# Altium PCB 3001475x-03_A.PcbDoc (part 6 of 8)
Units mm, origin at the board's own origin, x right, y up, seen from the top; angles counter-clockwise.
Board outline 100 x 72 mm, 12 copper layers (Top Layer, L2 GND, Layer 3, L4 GND, Layer 5, L6 PWR, L7 3V3, Layer 8, L9 GND, Layer 10, L11 GND, Bottom Layer), stack 1.735 mm thick; 428 components, 499 nets, 1973 pads, 1473 vias.
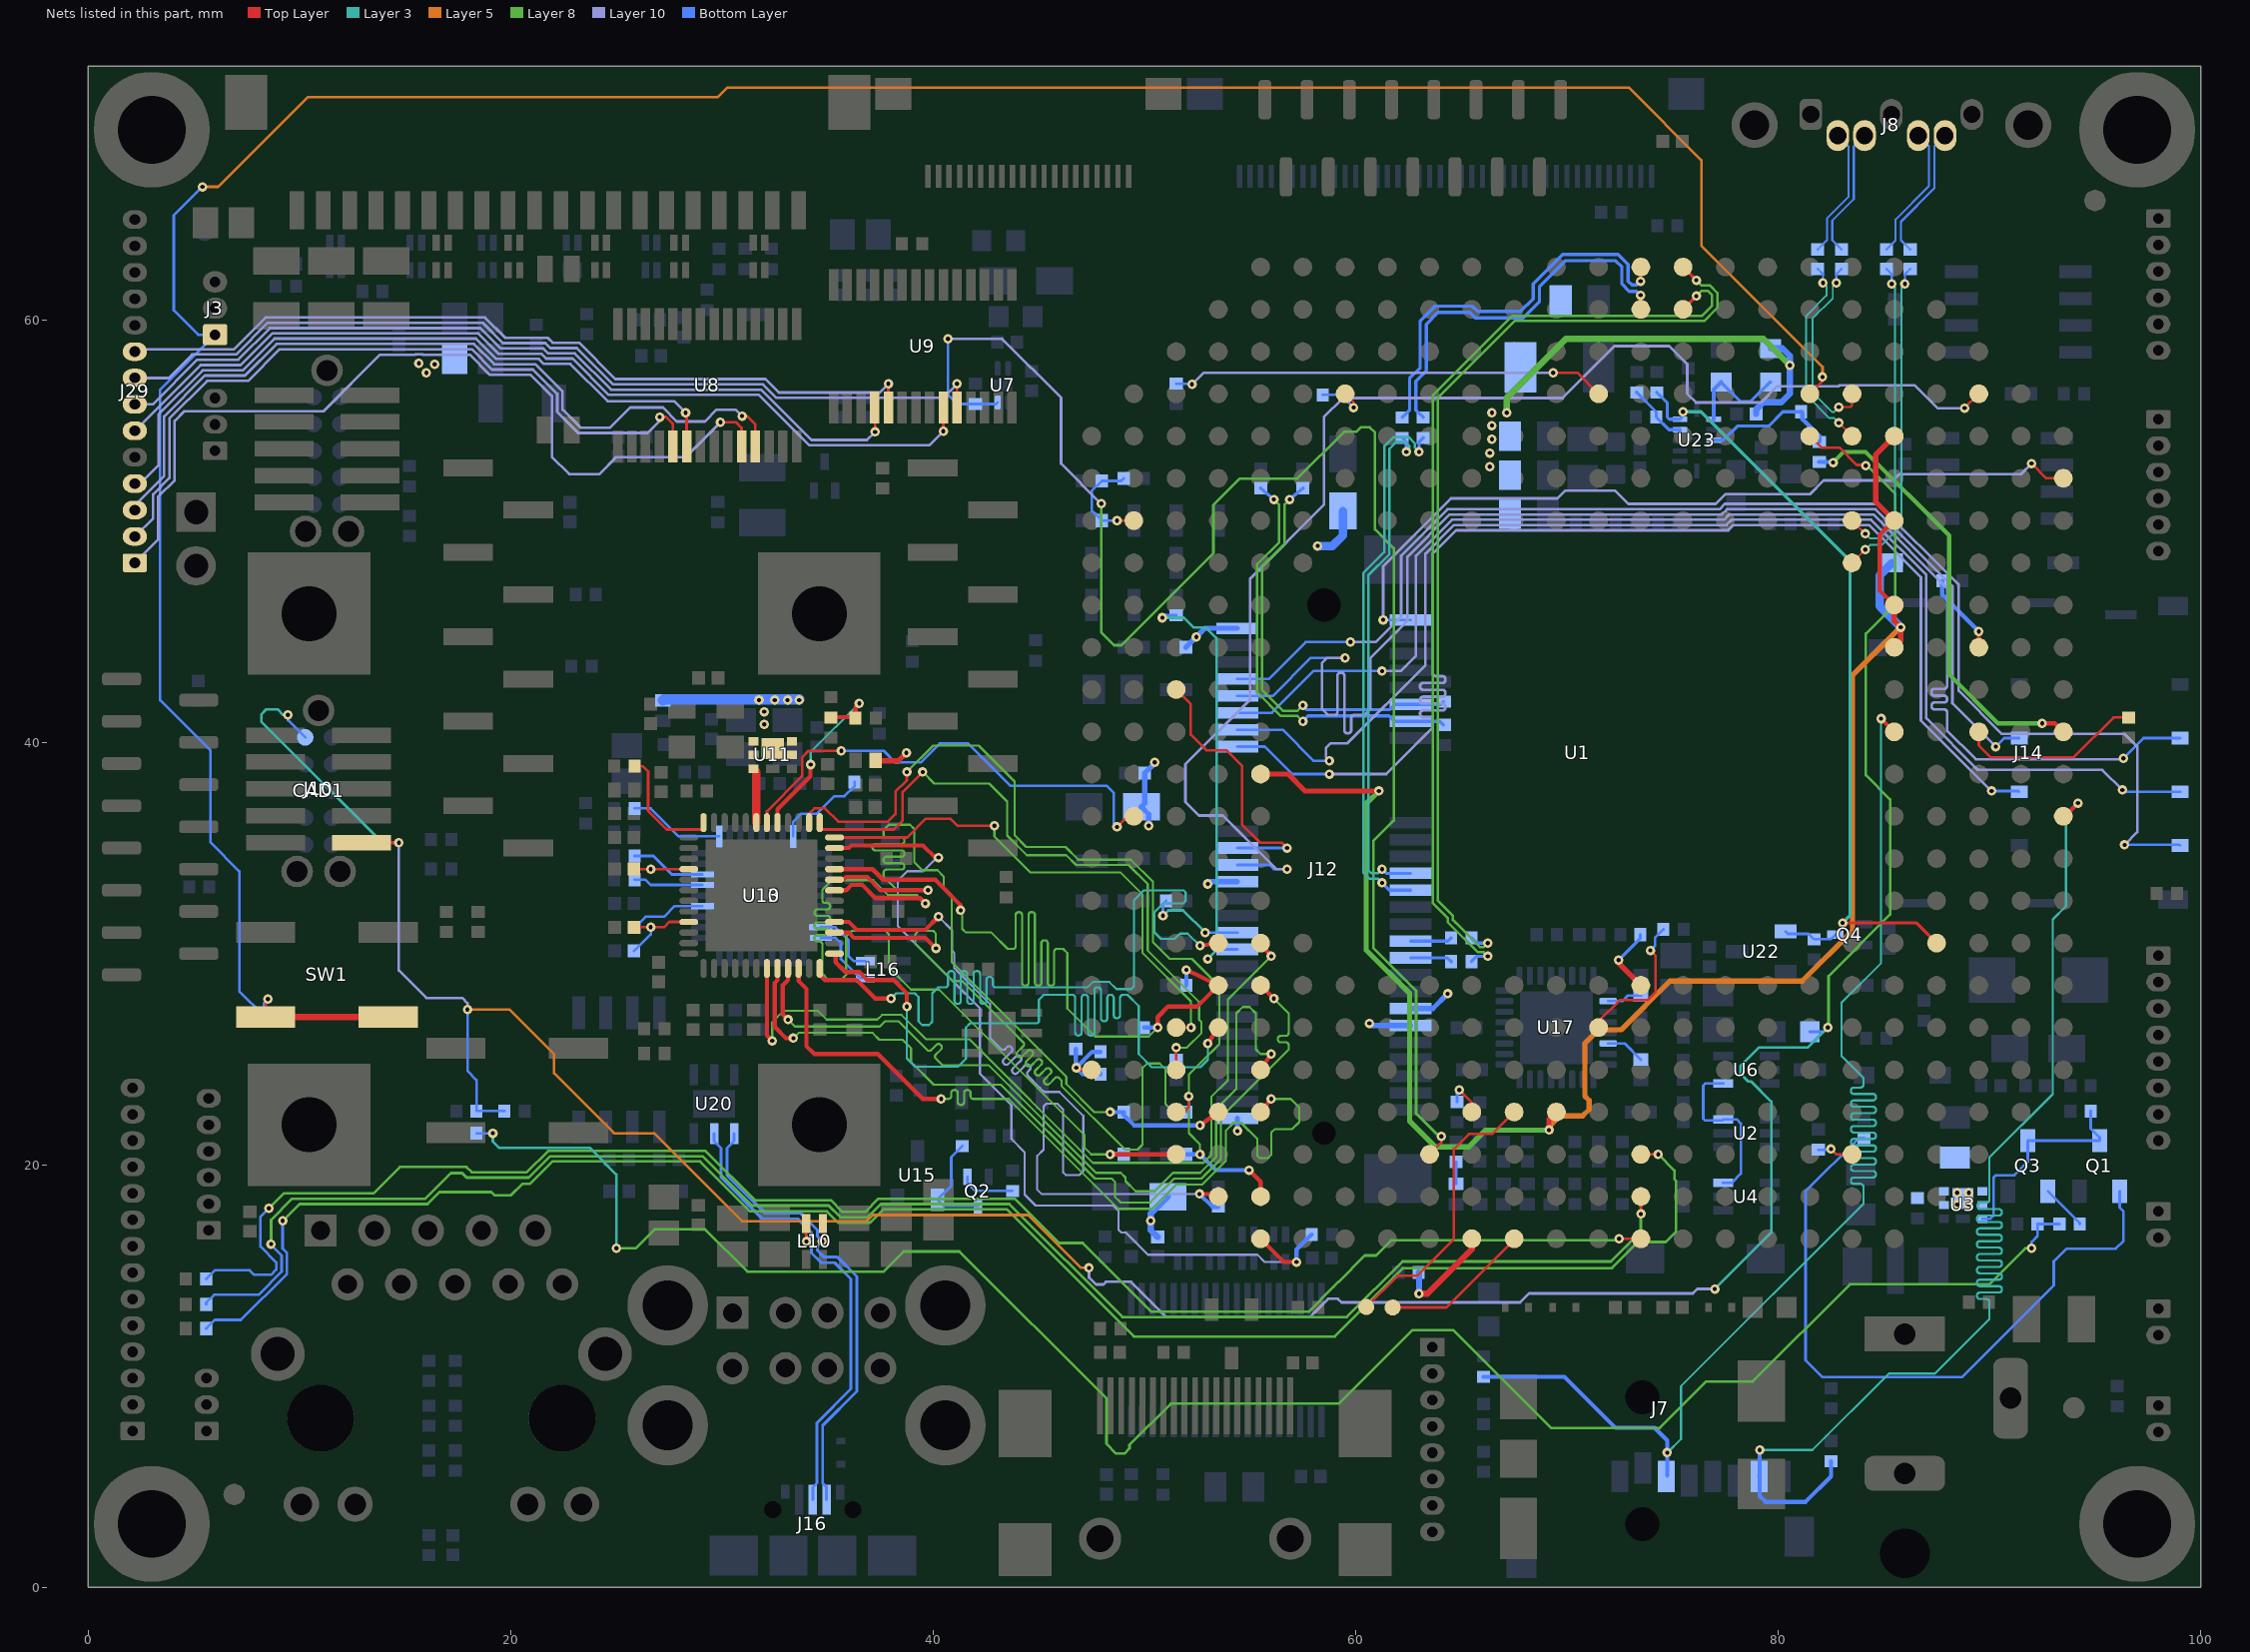
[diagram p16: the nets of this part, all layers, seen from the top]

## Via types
v1: diameter 0.45, hole 0.2, Top Layer to Bottom Layer, 1473 vias

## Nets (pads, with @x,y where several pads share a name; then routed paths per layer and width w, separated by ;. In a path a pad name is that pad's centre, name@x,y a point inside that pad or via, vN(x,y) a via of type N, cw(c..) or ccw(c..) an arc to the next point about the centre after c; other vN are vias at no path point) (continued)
NetL16_1: L16.1 U13.8 | length 3.2
  Bottom Layer w0.125: U13.8@34.675,31.25 35.375,31.25 36,30.625 36,29.875 36.225,29.65 L16.1@36.775,29.65
NetL16_4: L16.4 U13.9 | length 3.3
  Bottom Layer w0.125: U13.9@34.675,30.75 35.375,30.75 35.625,30.5 35.625,29.75 36.525,28.85 L16.4@36.775,28.85
NetL23_2: L23.2 R94.1 | length 1
  Bottom Layer w0.125: L23.2@64.75,19.105 R94.1@64.75,20.145
NetL24_1: L24.1 U17.2 | length 1.7
  Bottom Layer w0.125: U17.2@71.95,27.75 72.625,27.75 72.895,28.02 L24.1@73.5,28.02
NetL25_1: L25.1 U17.6 | length 1.9
  Bottom Layer w0.125: U17.6@71.95,25.75 72.73,25.75 L25.1@73.5,24.98
NetQ1_1: Q1.1 R13.2 | length 33
  Bottom Layer w0.125: R13.2@84.07,21.27 83.82,21.27 81.3,18.75 81.3,10.75 82.097,9.953 88.703,9.953 93.05,14.3 93.05,15.433 93.654,16.037 95.987,16.037 96.35,16.4 96.35,17.8 96.17,17.98 Q1.1@96.17,18.75
NetQ1_3: Q1.3 Q3.3 R14.2 U3.3 | length 10.3
  Bottom Layer w0.125: U3.3@89.66,17.45 90.05,17.45 90.2,17.6 90.2,19.4 90.313,19.513 91.183,19.513 91.82,20.15 Q3.3@91.82,21.15 Q1.3@95.22,21.15 95.22,21.3 94.8,21.72 R14.2@94.8,22.55
NetQ2_D: Q2.D R72.2 U15.G | length 5.1
  Bottom Layer w0.125: R72.2@41.375,20.895 40.85,20.37 40.85,19 U15.G@40.2,18.35 40.49,18.06 Q2.D@42.125,18.06
NetQ2_G: Q2.G R75.2 | length 2.6
  Bottom Layer w0.125: Q2.G@41.625,19.44 41.625,19.125 41.98,18.77 R75.2@43.75,18.77
NetQ3_1: Q3.1 R125.2 | length 2.2
  Bottom Layer w0.125: Q3.1@92.77,18.75 94.28,17.24 R125.2@94.28,17.2
NetQ4_D: Q4.D R128.2 U22.G | length 2.6
  Bottom Layer w0.125: U22.G@80.35,31.05 80.463,30.937 81.442,30.937 R128.2@81.7,30.68 82.49,30.68 Q4.D@82.71,30.9
NetR1_1: R1.1 R2.1 R3.1 U1.G2 | length 4.9
  Top Layer w0.125: v1(48.7,50.5) U1.G2@49.5,50.5
  Bottom Layer w0.125: v1(48.7,50.5) R1.1@47.98,50.5 47.5,50.98 47.5,51.895 R3.1@47.98,52.375 48.895,52.375 R2.1@49.02,52.5
NetR4_1: R4.1 U1.D13 | length 20.7
  Top Layer w0.125: v1(69.35,57.5) 70.5,57.5 U1.D13@71.5,56.5
  Layer 10 w0.125: v1(52.25,56.948) 52.802,57.5 v1(69.35,57.5)
  Bottom Layer w0.125: R4.1@51.5,56.98 52.218,56.98 v1(52.25,56.948)
NetR5_2: R5.2 U1.D7 | length 2.5
  Top Layer w0.125: U1.D7@59.5,56.5 59.9,56.1 v1(59.9,55.85)
  Bottom Layer w0.125: R5.2@58.43,56.45 59.3,56.45 v1(59.9,55.85)
NetR6_2: R6.2 R148.1 U3.1 U3.2 U3.5 U3.6 U3.7
  other v1: 88.475,18.125 89.025,18.125 88.475,18.675 89.025,18.675
NetR20_2: R20.2 U1.V14 | length 3.3
  Top Layer w0.254: v1(72.45,29.7) 72.45,29.55 U1.V14@73.5,28.5
  Bottom Layer w0.15: v1(72.45,29.7) 73.48,30.73 R20.2@73.48,30.9
NetR23_1: R23.1 U1.W13 | length 6.9
  Top Layer w0.125: U1.W13@71.5,26.5 71.5,26.8 72.5,27.8 73.8,27.8 74.2,28.2 74.2,29.9 v1(73.95,30.15)
  Bottom Layer w0.125: v1(73.95,30.15) 74.17,30.37 74.17,30.75 R23.1@74.57,31.15
NetR48_2: R48.2 R50.2 R154.2 U10.41 | length 9.2
  Top Layer w0.2: U10.41@32.625,36.2 32.625,36.832 34.19,38.397 34.19,38.94 v1(34.2,38.95) ; R50.2@35.15,41.18 35.17,41.2 36.27,41.2 R48.2@36.32,41.15 36.32,41.67 v1(36.5,41.85)
  Layer 3 w0.103: v1(34.2,38.95) 34.2,39.55 v1(36.5,41.85)
NetR49_2: R49.2 U10.48 | length 5.6
  Top Layer w0.125: R49.2@25.855,38.875 26.25,38.875 26.5,38.625 26.5,36.75 27.375,35.875 U10.48@29.125,35.875
NetR68_1: R68.1 U13.28 | length 4.6
  Bottom Layer w0.125: R68.1@25.855,36.875 26.625,36.875 27.95,35.55 U13.28@29.875,35.55
NetR70_2: R70.2 U13.35 | length 4.5
  Bottom Layer w0.125: U13.35@33.375,35.55 33.375,36.25 33.75,36.625 34.5,36.625 35.325,37.45 35.8,37.45 36.27,37.92 R70.2@36.27,38.125
NetR71_2: R71.2 U13.22 | length 3.6
  Bottom Layer w0.125: R71.2@25.875,31.25 26.375,31.75 27.25,31.75 27.75,32.25 U13.22@29.075,32.25
NetR73_2: R73.2 U13.24 | length 3.3
  Bottom Layer w0.125: R73.2@25.855,33.5 26.375,33.5 26.625,33.25 U13.24@29.075,33.25
NetR74_2: R74.2 U13.25 | length 7.2
  Bottom Layer w0.125: 26.75,34.625 R74.2@25.855,34.625 26.75,34.625 ; 26.75,34.625 27.625,33.75 ; 26.75,34.625 27.625,33.75 ; 27.625,33.75 U13.25@29.075,33.75 27.625,33.75
NetR80_2: R80.2 U1.M22 | length 8.8
  Top Layer w0.125: U1.M22@89.5,40.5 89.5,39.85 90.05,39.3 94,39.3 95.88,41.18 R80.2@96.6,41.18
NetR81_2: R81.2 U1.AD10 | length 4.9
  Top Layer w0.3: v1(63,13.9) 63.4,13.9 65.5,16 U1.AD10@65.5,16.5
  Bottom Layer w0.3: R81.2@62.98,14.9 63,14.88 v1(63,13.9)
NetR82_2: R82.2 U1.AA10 | length 1.9
  Top Layer w0.125: v1(64.9,23.55) 65.5,22.95 U1.AA10@65.5,22.5
  Bottom Layer w0.125: R82.2@64.8,22.98 64.8,23.45 v1(64.9,23.55)
NetR83_2: R83.2 U1.AA12 U1.E20 U1.G20 U1.J20 U1.K20 U1.N5 | length 82.1
  Top Layer w0.2: U1.J20@85.5,46.5 84.806,47.194 84.806,49.805 U1.G20@85.5,50.5
  Top Layer w0.25: U1.N5@55.5,38.5 56.8,38.5 57.6,37.7 v1(61.1,37.7) ; v1(69.15,21.65) 69.15,22.15 U1.AA12@69.5,22.5 ; U1.K20@85.5,44.5 85.8,44.8 v1(85.8,45.45) 85.5,45.75 U1.J20@85.5,46.5 ; U1.G20@85.5,50.5 84.625,51.375 84.625,53.625 U1.E20@85.5,54.5
  Layer 8 w0.25: v1(61.1,37.7) 60.5,37.1 60.5,30.166 62.55,28.116 62.55,22.075 63.775,20.85 65.35,20.85 66.15,21.65 v1(69.15,21.65)
  Layer 5 w0.25: v1(69.15,21.65) 69.15,21.8 69.675,22.325 70.747,22.325 71.05,22.628 71.05,23.05 70.85,23.25 70.85,25.75 71.5,26.4 72.572,26.4 74.872,28.7 81.141,28.7 83.525,31.084 83.525,43.175 v1(85.8,45.45)
  Bottom Layer w0.4: R83.2@85.4,48.5 84.8,47.9 84.8,46.45 v1(85.8,45.45)
NetR137_1: R137.1 R138.2 U23.4 | length 2.9
  Bottom Layer w0.15: R138.2@73.3,56.57 74.23,55.64 R137.1@74.23,55.4 74.83,54.8 U23.4@75.35,54.8
NetR140_1: R140.1 R141.2 U23.9 | length 6.5
  Bottom Layer w0.15: U23.9@76.95,54.3 77.4,54.3 78.075,54.975 79.55,54.975 80.225,55.65 R140.1@81.096,55.65
  Bottom Layer w0.2: R140.1@81.096,55.65 81.15,55.596 81.15,55.3 81.95,54.5 R141.2@81.95,54.23
NetR143_1: R143.1 R144.2 U23.7 | length 5
  Bottom Layer w0.15: R144.2@77.3,57.05 78.225,56.125 78.676,56.125 79.601,57.05 R143.1@79.65,57.05
  Bottom Layer w0.2: U23.7@76.95,55.3 76.95,56.7 R144.2@77.3,57.05
NetR153_1: R153.1 U1.AB19 | length 1.7
  Top Layer w0.125: v1(82.5,20.75) 82.75,20.5 U1.AB19@83.5,20.5
  Bottom Layer w0.125: R153.1@81.9,20.72 82.47,20.72 v1(82.5,20.75)
NetTP1_1: TP1.1 U1.AA11 | length 13.3
  Top Layer w0.125: TP1.1@60.5,13.275 61.975,14.75 62.9,14.75 64.65,16.5 64.65,20.75 65.36,21.46 66.46,21.46 U1.AA11@67.5,22.5
NetTP2_1: TP2.1 U1.AD11 | length 7.1
  Top Layer w0.125: TP2.1@61.75,13.25 64.3,13.25 67.5,16.45 U1.AD11@67.5,16.5
NetU2_6: U2.6 U4.6 U6.4 | length 7.9
  Bottom Layer w0.125: U4.6@77.4,19.15 77.808,19.15 78.238,19.579 78.238,21.962 78.05,22.15 U2.6@77.4,22.15 77.35,22.1 76.55,22.1 76.45,22.2 76.45,23.75 76.55,23.85 U6.4@77.4,23.85
NetU10_43: U10.43 U11.3 | length 2.6
  Top Layer w0.4: U11.3@31.49,38.75 31.625,38.615 U10.43@31.625,36.2
ON/OFF: J3.1 R147.1 SW1.3 SW1.4 U1.D18 | length 139.8
  Top Layer w0.125: SW1.3@8.4,27 8.4,27.75 v1(8.5,27.85) ; U1.D18@81.5,56.5 82.1,57.1 v1(82.1,57.3)
  Top Layer w0.3: SW1.3@8.4,27 SW1.4@14.2,27
  Layer 5 w0.125: v1(5.4,66.3) 6.15,66.3 10.4,70.55 29.8,70.55 30.25,71 72.925,71 76.363,67.562 76.363,63.512 82.1,57.775 v1(82.1,57.3)
  Bottom Layer w0.125: v1(5.4,66.3) 4.046,64.946 4.046,60.454 5.2,59.3 J3.1@6,59.3 3.4,56.7 3.4,42 5.775,39.625 5.775,35.275 7.15,33.9 7.15,28.22 R147.1@8.32,27.05 8.32,27.67 v1(8.5,27.85)
OTGD_N: J16.2 L10.2 U20.4 | length 23.2
  Top Layer w0.137: v1(34.75,16.375) 34.75,16.673 34.775,16.698 L10.2@34.775,17.225
  Bottom Layer w0.137: U20.4@30.575,21.475 30.575,21.125 30.24,20.79 30.24,19.51 32.02,17.73 33.701,17.73 34.515,16.916 34.515,16.61 v1(34.75,16.375) 34.515,16.14 34.515,15.95 34.815,15.65 35.446,15.65 36.38,14.716 36.38,9.28 34.765,7.665 34.765,4.935 34.95,4.75 J16.2@34.95,4.15
OTGD_P: J16.3 L10.3 U20.5 | length 23.2
  Top Layer w0.137: L10.3@33.975,17.225 33.975,16.698 34,16.673 v1(34,16.375)
  Bottom Layer w0.137: U20.5@29.625,21.475 29.625,21.125 29.96,20.79 29.96,19.394 31.904,17.45 33.585,17.45 34.235,16.8 34.235,16.61 v1(34,16.375) 34.235,16.14 34.235,15.834 34.699,15.37 35.33,15.37 36.1,14.6 36.1,9.396 34.485,7.781 34.485,4.935 34.3,4.75 J16.3@34.3,4.15
PCIE_DIS_N: J12.20 U1.L3 | length 13.2
  Top Layer w0.125: U1.L3@51.5,42.5 52.187,41.813 52.187,40.363 52.925,39.625 53.875,39.625 54.625,38.875 54.625,36.1 55.475,35.25 56.5,35.25 v1(56.75,35)
  Bottom Layer w0.125: J12.20@54.4,35 v1(56.75,35)
PCIE_I2C_SCL: J12.30 R95.2 | length 4.8
  Layer 3 w0.125: v1(50.875,31.8) 51.125,32.05 51.825,32.05 v1(52.875,31)
  Bottom Layer w0.125: v1(50.875,31.8) 50.875,32.355 R95.2@51.02,32.5 ; v1(52.875,31) J12.30@54.4,31
PCIE_I2C_SDA: J12.32 R96.2 | length 20.6
  Layer 3 w0.125: v1(50.85,45.9) 51.867,45.9 52.329,45.437 52.913,45.437 53.413,44.937 53.413,30.163 v1(53,29.75)
  Bottom Layer w0.125: v1(50.85,45.9) 50.97,46.02 R96.2@51.5,46.02 ; v1(53,29.75) 53.45,30.2 J12.32@54.4,30.2
PCIE_RESET_N: J12.22 U1.D22 | length 64.9
  Top Layer w0.125: v1(88.825,55.825) U1.D22@89.5,56.5
  Layer 10 w0.125: v1(56.75,34) 56.25,34 53.713,36.537 52.579,36.537 51.937,37.179 51.937,38.971 55,42.033 55,47.755 58.495,51.25 58.495,55.395 59.4,56.3 69.794,56.3 72.257,58.763 74.837,58.763 75.7,57.9 75.7,56.5 76.113,56.087 79.187,56.087 79.963,56.863 82.863,56.863 82.913,56.913 86.462,56.913 87.55,55.825 v1(88.825,55.825)
  Bottom Layer w0.125: J12.22@54.4,34.2 55.925,34.2 56.125,34 v1(56.75,34)
PCIE_RX_N: R44.1 U1.A14 | length 19.1
  Top Layer w0.157: v1(73.487,61.83) 73.5,61.843 U1.A14@73.5,62.5
  Bottom Layer w0.157: R44.1@62.2,55.38 62.55,55.73 62.55,57.224 63.05,57.724 63.05,59.95 63.75,60.65 65.524,60.65 65.774,60.4 67.026,60.4 67.8,60.4 68.4,61 68.4,61.7 69.8,63.1 72.424,63.1 72.9,62.624 72.9,61.824 73.074,61.65 73.307,61.65 v1(73.487,61.83)
PCIE_RX_P: R47.1 U1.B14 | length 18.6
  Top Layer w0.157: v1(73.487,61.17) 73.5,61.157 U1.B14@73.5,60.5
  Bottom Layer w0.157: R47.1@63.2,55.38 62.85,55.73 62.85,57.1 63.35,57.6 63.35,59.8 63.9,60.35 65.4,60.35 65.65,60.1 67.15,60.1 67.924,60.1 68.7,60.876 68.7,61.576 69.924,62.8 72.3,62.8 72.6,62.5 72.6,61.7 72.95,61.35 73.307,61.35 v1(73.487,61.17)
PCIE_TX_N: R51.1 U1.A15 | length 46.3
  Top Layer w0.157: U1.A15@75.5,62.5 v1(76.125,61.875)
  Layer 8 w0.119: 63.894,49.7 63.894,49.994 ; v1(66.25,30.5) 66.059,30.309 65.886,30.309 64.721,31.474 64.604,31.592 64.604,31.792 63.894,32.501 63.894,49.994 ; v1(76.125,61.875) 76.378,61.622 76.776,61.622 77.121,61.278 77.121,60.569 77.049,60.498 76.501,59.95 69.195,59.95 67.521,59.95 63.894,56.323 63.894,55.994 63.894,49.994
  Bottom Layer w0.157: R51.1@65.48,30.75 65.73,30.5 v1(66.25,30.5)
PCIE_TX_P: R52.1 U1.B15 | length 46.4
  Top Layer w0.157: U1.B15@75.5,60.5 v1(76.125,61.125)
  Layer 8 w0.119: 63.65,49.7 63.65,50.095 ; v1(66.25,29.875) 66.059,30.065 65.784,30.065 64.36,31.49 64.36,31.69 63.65,32.4 63.65,50.095 ; v1(76.125,61.125) 76.378,61.378 76.675,61.378 76.877,61.176 76.877,60.671 76.4,60.194 69.094,60.194 67.42,60.194 63.65,56.424 63.65,56.095 63.65,50.095
  Bottom Layer w0.157: R52.1@65.48,29.625 65.73,29.875 v1(66.25,29.875)
PCIE_UIM_CLK: J12.12 J14.3 | length 62.9
  Layer 10 w0.125: v1(61.25,43.375) 62.125,43.375 62.852,44.102 62.852,48.834 64.555,50.538 77.438,50.538 77.688,50.788 84.505,50.788 88,47.293 88,42.684 cw(c87.854,42.684) 87.854,42.538 87.409,42.538 ccw(c87.409,42.391) 87.262,42.391 87.262,42.359 ccw(c87.409,42.359) 87.409,42.213 87.854,42.213 cw(c87.854,42.066) 88,42.066 88,42.034 cw(c87.854,42.034) 87.854,41.888 87.409,41.888 ccw(c87.409,41.741) 87.262,41.741 87.262,41.709 ccw(c87.409,41.709) 87.409,41.563 87.854,41.563 cw(c87.854,41.416) 88,41.416 88,40.55 89.35,39.2 96.3,39.2 v1(96.35,39.25)
  Bottom Layer w0.125: J12.12@54.4,41.4 56.025,41.4 58,43.375 v1(61.25,43.375) ; v1(96.35,39.25) 97.3,40.2 J14.3@99.03,40.2
PCIE_UIM_DATA: J12.10 J14.7 | length 63
  Layer 10 w0.125: v1(59.5,44) 58.65,44 58.4,43.75 58.4,41.6 58.7,41.3 58.991,41.3 ccw(c58.991,41.446) 59.137,41.446 59.137,43.154 cw(c59.284,43.154) 59.284,43.3 59.316,43.3 cw(c59.316,43.154) 59.462,43.154 59.462,40.577 ccw(c59.609,40.577) 59.609,40.43 59.641,40.43 ccw(c59.641,40.577) 59.788,40.577 59.788,41.154 cw(c59.934,41.154) 59.934,41.3 60.4,41.3 60.7,41.6 60.7,44 62.45,45.75 62.45,48.786 64.452,50.788 77.334,50.788 77.584,51.038 84.609,51.038 88.25,47.396 88.25,41.85 v1(90.3,39.8)
  Bottom Layer w0.125: J12.10@54.4,42.2 56.075,42.2 57.875,44 v1(59.5,44) ; v1(90.3,39.8) 90.7,40.2 J14.7@91.41,40.2
PCIE_UIM_PWR: J12.8 J14.1 | length 63
  Layer 10 w0.125: v1(59.75,44.75) 60.95,44.75 62.15,45.95 62.15,48.839 64.348,51.038 77.23,51.038 77.48,51.288 84.712,51.288 88.55,47.45 88.55,42.45 90.6,40.4 96.4,40.4 97,39.8 97,35.75 v1(96.4,35.15)
  Bottom Layer w0.125: J12.8@54.4,43 55.875,43 57.625,44.75 v1(59.75,44.75) ; v1(96.4,35.15) 99,35.15 J14.1@99.03,35.12
PCIE_UIM_RST: J12.14 J14.2 | length 62.9
  Layer 10 w0.125: v1(58.75,39.125) 58.6,39.275 58.6,39.75 58.8,39.95 59.586,39.95 63.3,43.664 63.3,48.929 64.659,50.288 77.541,50.288 77.791,50.538 84.402,50.538 87.013,47.927 87.013,41.137 89.45,38.7 95.35,38.7 v1(96.3,37.75)
  Bottom Layer w0.125: J12.14@54.4,40.6 56.55,40.6 58.025,39.125 58.25,39.125 v1(58.75,39.125) ; v1(96.3,37.75) 96.39,37.66 J14.2@99.03,37.66
PCIE_UIM_VPP: J12.16 J14.6 | length 62.9
  Layer 10 w0.125: v1(58.75,38.5) 61.45,38.5 63.625,40.675 ; 63.535,40.585 63.65,40.7 63.65,40.862 63.65,41.041 ccw(c63.504,41.041) 63.504,41.187 63.196,41.187 cw(c63.196,41.334) 63.05,41.334 63.05,41.366 cw(c63.196,41.366) 63.196,41.512 63.65,41.512 64.104,41.512 ccw(c64.104,41.659) 64.25,41.659 64.25,41.691 ccw(c64.104,41.691) 64.104,41.837 63.65,41.837 63.196,41.837 cw(c63.196,41.984) 63.05,41.984 63.05,42.016 cw(c63.196,42.016) 63.196,42.162 63.65,42.162 64.104,42.162 ccw(c64.104,42.309) 64.25,42.309 64.25,42.341 ccw(c64.104,42.341) 64.104,42.487 63.65,42.487 63.196,42.487 cw(c63.196,42.634) 63.05,42.634 63.05,42.666 cw(c63.196,42.666) 63.196,42.813 63.65,42.813 64.104,42.813 ccw(c64.104,42.959) 64.25,42.959 64.25,42.991 ccw(c64.104,42.991) 64.104,43.138 63.796,43.138 cw(c63.796,43.284) 63.65,43.284 63.65,43.3 63.65,48.925 64.762,50.038 77.645,50.038 77.895,50.288 84.298,50.288 86.763,47.823 86.763,41.034 90.096,37.7 v1(90.1,37.7)
  Bottom Layer w0.125: J12.16@54.4,39.8 55.7,39.8 57,38.5 v1(58.75,38.5) ; v1(90.1,37.7) 91.37,37.7 J14.6@91.41,37.66
PCIE_VCC: C34.1 C35.1 C36.1 C37.2 C38.2 C39.2 C108.2 C115.2 C116.2 C117.2 C119.2 J12.2 J12.24 J12.39 J12.41 J12.52 L1.2 L29.1 R143.2 | length 38
  Layer 8 w0.3: v1(67.15,55.6) 67.15,56.3 69.95,59.1 79.3,59.1 v1(80.55,57.85)
  Bottom Layer w0.25: v1(50.2,36.05) 50.2,36.6 C35.1@49.85,36.95 50.01,37.11 C39.2@50.01,38.55 50.49,39.03 v1(50.49,39.058) ; C37.2@51.96,44.5 v1(52.454,44.994) 52.86,45.4 J12.2@54.4,45.4 ; v1(53,33.3) 53.1,33.4 J12.24@54.4,33.4 ; v1(54.4,21.6) J12.52@54.4,22.2 ; v1(60.65,26.7) 60.75,26.6 J12.41@62.6,26.6 ; J12.39@62.6,27.4 63.65,27.4 v1(64.35,28.1) ; C108.2@78.96,55.55 C108.2@78.975,55.565
  Bottom Layer w0.3: C38.2@50.625,16.585 50.3,16.91 v1(50.3,17.35) 50.3,17.7 C34.1@51.1,18.5 ; C108.2@78.96,55.55 78.96,55.76 79.3,56.1 80.15,56.1 80.55,56.5 v1(80.55,57.85) 80.55,58.3 80.2,58.65 R143.2@79.65,58.65
  Bottom Layer w0.4: v1(58.2,49.3) 58.9,49.3 59.4,49.8 C36.1@59.4,50.95
  other v1: 66.35,53.05 66.35,53.7 66.45,54.35 66.45,55 66.45,55.6 16,57.5 16.4,57.9 15.65,57.95
PCIE_VCC_EN: R141.1 U1.M24 | length 21.1
  Top Layer w0.2: v1(92.5,40.9) 93.1,40.9 U1.M24@93.5,40.5
  Layer 8 w0.2: v1(82.6,53.25) 83.1,53.75 84.136,53.75 88.1,49.786 88.1,43.2 90.4,40.9 v1(92.5,40.9)
  Bottom Layer w0.2: R141.1@81.95,53.27 82.58,53.27 v1(82.6,53.25)
PCIE_VCC_PG: R139.2 U1.U21 U23.5 | length 35.4
  Top Layer w0.15: v1(83.05,31.45) 86.55,31.45 U1.U21@87.5,30.5
  Layer 3 w0.15: v1(75.5,55.65) 76.35,55.65 83.4,48.6 83.4,31.8 v1(83.05,31.45)
  Bottom Layer w0.15: R139.2@74.25,56.57 74.75,56.07 74.75,55.4 74.85,55.3 U23.5@75.35,55.3 75.5,55.45 v1(75.5,55.65)
PCIE_WAKE_N: J12.1 U1.F24 | length 38.9
  Top Layer w0.125: v1(92,53.2) 92.7,52.5 U1.F24@93.5,52.5
  Layer 10 w0.125: v1(61.3,45.8) 61.3,48.343 64.507,51.55 69.55,51.55 69.913,51.913 72.287,51.913 72.912,51.288 77.038,51.288 77.5,51.75 81.5,51.75 82.15,52.4 85.45,52.4 85.75,52.7 91.5,52.7 v1(92,53.2)
  Bottom Layer w0.125: v1(61.3,45.8) J12.1@62.6,45.8
PCIECLK_N: C31.2 J12.11 R43.2 | length 19.7
  Layer 8 w0.119: v1(56.875,51.5) 56.622,51.247 56.622,49.377 55.575,48.33 55.575,42.475 56.553,41.497 57.247,41.497 v1(57.5,41.75)
  Bottom Layer w0.157: v1(56.875,51.5) C31.2@57.5,52.04 ; v1(57.5,41.75) 57.7,41.55 61.6,41.55 61.85,41.8 J12.11@62.6,41.8 64.03,41.8 R43.2@64.15,41.92
PCIECLK_P: C32.2 J12.13 R42.2 | length 20.2
  Layer 8 w0.119: v1(56.125,51.5) 56.378,51.247 56.378,49.478 55.331,48.431 55.331,42.374 56.452,41.253 57.247,41.253 v1(57.5,41)
  Bottom Layer w0.157: C32.2@55.5,52.04 v1(56.125,51.5) ; v1(57.5,41) 57.75,41.25 61.575,41.25 61.825,41 J12.13@62.6,41 63.98,41 R42.2@64.15,40.83
PCIERX_N: J12.23 R44.2 | length 24.8
  Layer 3 w0.119: v1(61.25,34) 61.047,33.797 60.75,33.797 60.6,33.947 60.6,47.914 61.594,48.908 61.594,53.894 61.9,54.2 62.35,54.2 62.55,54 62.55,53.9 v1(62.4,53.75)
  Bottom Layer w0.157: v1(61.25,34) 61.45,33.8 J12.23@62.6,33.8 ; R44.2@62.2,54.42 62.4,54.22 v1(62.4,53.75)
PCIERX_P: J12.25 R47.2 | length 26.2
  Layer 3 w0.119: v1(61.25,33.35) 61.047,33.553 60.649,33.553 60.356,33.846 60.356,48.015 61.35,49.009 61.35,54 61.8,54.45 62.5,54.45 62.8,54.15 62.8,53.95 v1(63,53.75)
  Bottom Layer w0.157: v1(61.25,33.35) 61.6,33 J12.25@62.6,33 ; v1(63,53.75) 63,54.22 R47.2@63.2,54.42
PCIETX_N: J12.31 R51.2 | length 2
  Bottom Layer w0.157: J12.31@62.6,30.6 64.37,30.6 R51.2@64.52,30.75
PCIETX_P: J12.33 R52.2 | length 2
  Bottom Layer w0.157: J12.33@62.6,29.8 64.345,29.8 R52.2@64.52,29.625
PMIC_ADCIN1: R204.1 U1.AB14 | length 85.6
  Top Layer w0.125: U1.AB14@73.5,20.5 v1(74.325,20.5) v1@74.375,20.5
  Layer 8 w0.125: v1(9.2,17.35) 10,18.15 16.063,18.15 16.626,18.713 19.079,18.713 19.229,18.562 20.012,18.562 20.55,19.1 20.907,19.1 21.97,20.163 28.962,20.163 31.325,17.8 34.969,17.8 35.494,17.275 37.025,17.275 37.65,17.9 43.475,17.9 49.5,11.875 59.012,11.875 62.249,15.113 72.127,15.113 73.364,16.35 74.683,16.35 75.163,16.829 75.163,19.254 75.087,19.329 75.087,19.738 v1(74.325,20.5)
  Bottom Layer w0.125: R204.1@5.58,12.25 5.993,12.663 7.22,12.663 9.4,14.842 9.4,15.832 9.2,16.032 v1(9.2,17.35)
PMIC_ADCIN2: R205.1 U1.AC14 | length 80.2
  Top Layer w0.125: v1(73.5,17.675) U1.AC14@73.5,18.5
  Layer 8 w0.125: v1(8.651,16.25) 8.651,17.401 9.65,18.4 15.95,18.4 17.163,19.613 17.696,19.613 17.908,19.4 20.854,19.4 21.866,20.413 29.087,20.413 31.425,18.075 35.048,18.075 35.598,17.525 36.9,17.525 37.525,18.15 43.6,18.15 48.95,12.8 59.583,12.8 62.213,15.429 72.09,15.429 73.5,16.839 v1(73.5,17.675)
  Bottom Layer w0.125: R205.1@5.58,13.4 5.58,13.48 5.95,13.85 8.054,13.85 9.15,14.946 9.15,15.713 8.651,16.213 v1(8.651,16.25)
PMIC_ADCIN3: R206.1 U1.AD14 | length 78.4
  Top Layer w0.125: v1(72.475,16.5) U1.AD14@73.5,16.5
  Layer 8 w0.125: v1(8.55,17.95) 9.25,18.65 13.492,18.65 14.742,19.9 17.9,19.9 18.15,19.65 20.75,19.65 21.763,20.663 29.212,20.663 31.55,18.325 35.151,18.325 35.701,17.775 36.775,17.775 37.4,18.4 43.85,18.4 45.95,16.3 47.075,16.3 50.325,13.05 50.346,13.05 50.936,13.05 57.773,13.05 58.937,14.215 58.937,14.221 59.179,14.463 59.185,14.463 60.435,15.712 60.965,15.712 61.678,16.425 72.4,16.425 v1(72.475,16.5)
  Bottom Layer w0.125: R206.1@5.58,14.6 5.993,15.013 7.637,15.013 7.85,14.8 8.651,14.8 8.9,15.05 8.9,15.383 8.15,16.133 8.15,17.55 v1(8.55,17.95)
POR_N: CAD1.10 J10.10 R7.1 R15.1 R123.2 U1.E18 | length 148.4
  Top Layer w0.125: U1.E18@81.5,54.5 82.05,53.95 82.9,53.95 83.718,53.132 v1@83.974,53.132 ; v1@83.974,53.132 84.118,53.132 v1(84.15,53.1) 84.006,53.1 v1@83.974,53.132
  Top Layer w0.15: J10.10@12.932,35.26 12.942,35.25 v1(14.7,35.25)
  Layer 8 w0.125: v1(82.35,26.5) 82.388,26.538 82.388,28.938 85.3,31.85 85.3,37.3 84.15,38.45 84.15,45.146 85.55,46.546 85.55,51.758 84.208,53.1 v1(84.15,53.1)
  Layer 5 w0.125: v1(17.95,27.35) 19.95,27.35 22.05,25.25 22.05,24.343 24.893,21.5 26.775,21.5 30.938,17.337 36.845,17.337 37.132,17.625 44.5,17.625 47,15.125 v1(47.375,15.125)
  Layer 10 w0.125: v1(14.7,35.25) 14.7,29.2 16,27.9 17.7,27.9 17.95,27.65 v1(17.95,27.35) ; v1(47.375,15.125) 47.375,14.667 47.704,14.337 48.054,14.337 48.179,14.463 49.362,14.463 51.025,12.8 57.839,12.8 58.702,13.663 59.154,13.663 59.329,13.487 67.787,13.487 68.213,13.913 75.963,13.913 76.175,14.125 v1(77,14.125)
  Layer 3 w0.125: v1(9.45,41.3) 9.22,41.3 8.958,41.563 8.429,41.563 8.187,41.321 8.187,40.979 13.917,35.25 v1(14.7,35.25) ; v1(77,14.125) 79.675,16.8 79.675,23 78.725,23.95 78.592,23.95 78.212,24.329 78.212,24.671 79.104,25.563 81.413,25.563 v1(82.35,26.5)
  Bottom Layer w0.125: v1(9.45,41.3) 9.45,41.055 CAD1.10@10.265,40.24 ; v1(17.95,27.35) 17.95,24.45 18.38,24.02 R123.2@18.38,22.55 R7.1@19.695,22.55 ; R15.1@81.5,26.3 82.15,26.3 v1(82.35,26.5)
PWR_EN: R22.1 U1.AB9 U7.4 | length 79.1
  Top Layer w0.125: U1.AB9@63.5,20.5 64.05,21.05 v1(64.05,21.35)
  Layer 8 w0.125: v1(47.95,51.3) 47.95,45.217 48.567,44.6 48.912,44.6 53.262,48.95 53.262,51.237 54.512,52.487 57.238,52.487 59.45,54.7 60.033,54.7 60.246,54.913 60.671,54.913 60.913,54.671 60.913,50.077 61.8,49.189 61.8,36.3 60.837,35.337 60.837,30.27 62.863,28.245 62.863,22.438 63.95,21.35 v1(64.05,21.35)
  Layer 10 w0.125: v1(40.7,59.1) 43.267,59.1 46.05,56.317 46.05,53.2 v1(47.95,51.3)
  Bottom Layer w0.125: v1(40.7,59.1) 40.7,56.45 41.13,56.02 R22.1@42,56.02 42.98,56.02 U7.4@43.05,56.09
RGMII_1V2: C57.2 C58.2 C59.2 L4.2 L5.1 U10.4 U10.9 U11.1 U11.2 U11.5 U11.6 U11.7 | length 14.9
  Top Layer w0.125: C58.2@25.835,31.25 v1(26.625,31.25) 27.25,31.25 27.5,31.5 U10.9@28.425,31.5 ; C59.2@25.835,34 v1(26.625,34) U10.4@28.425,34
  Top Layer w0.25: L4.2@37.23,39.125 38.35,39.125 v1(38.725,39.5)
  Bottom Layer w0.125: C57.2@25.835,30.125 26.625,30.915 v1(26.625,31.25)
  Bottom Layer w0.5: L5.1@27.2,41.98 27.245,42.025 v1@33.65,42.025
  other v1: 32,40.85 32,41.45 31.75,42 32.5,42 33.1,42 33.65,42
RGMII_INT_N: R40.1 U1.AA3 U10.38 | length 38.3
  Top Layer w0.125: U10.38@34.125,36.2 34.125,36.625 34.375,36.875 34.875,36.875 35.5,36.25 37.85,36.25 38.213,36.613 38.213,37.666 38.75,38.204 v1(38.75,38.6) ; U1.AA3@51.5,22.5 51.875,22.5 52.1,22.725 v1(52.1,23.25)
  Layer 8 w0.103: v1(38.75,38.6) 40,39.85 42.15,39.85 43.85,38.15 43.85,35.6 44.4,35.05 46.262,35.05 46.862,34.45 49.35,34.45 50.4,33.4 50.4,30.55 51.2,29.75 52.25,29.75 53.55,28.45 53.55,25.717 53.171,25.337 53.15,25.337 52.1,24.287 v1(52.1,23.25)
  Bottom Layer w0.125: R40.1@51.98,22.5 52.1,22.62 v1(52.1,23.25)
RGMII_MDC: U1.W3 U10.36 | length 24.7
  Top Layer w0.125: U10.36@35.325,35.5 38.763,35.5 39.65,36.387 40.813,36.387 41.151,36.05 v1(42.9,36.05) ; U1.W3@51.5,26.5 v1(52.2,26.5)
  Layer 8 w0.103: v1(42.9,36.05) 42.9,35.55 44.613,33.837 48.871,33.837 49.9,32.808 49.9,30.046 52.2,27.746 v1(52.2,26.5)
RGMII_MDIO: R41.1 U1.Y3 U10.37 | length 32.1
  Top Layer w0.125: U10.37@34.625,36.2 34.625,35.875 38.125,35.875 38.55,36.3 38.55,37.65 v1(39.5,38.6) ; U1.Y3@51.5,24.5 v1(51.5,25.55)
  Layer 8 w0.103: v1(39.5,38.6) 40.05,38.05 42.649,38.05 43.5,37.199 43.5,35.596 44.434,34.663 46.296,34.663 46.758,34.2 49.246,34.2 50.15,33.296 50.15,30.15 52.587,27.713 52.587,26.867 52.7,26.754 52.7,26.25 52,25.55 v1(51.5,25.55)
  Bottom Layer w0.125: R41.1@51.5,24.98 v1(51.5,25.55)
RGMII_RD0: R60.1 U1.AA4 U10.32 | length 41.3
  Top Layer w0.2: U10.32@35.325,33.5 35.75,33.5 35.875,33.625 36.875,33.625 37.5,33 v1(39.75,33) ; v1(52.625,21.875) U1.AA4@53.5,22.5
  Layer 8 w0.103: v1(39.75,33) 38.3,33 37.65,33.65 37.65,33.841 cw(c37.787,33.841) 37.787,33.978 38.494,33.978 ccw(c38.494,34.115) 38.631,34.115 38.631,34.145 ccw(c38.494,34.145) 38.494,34.282 37.787,34.282 cw(c37.787,34.419) 37.65,34.419 37.65,34.449 cw(c37.787,34.449) 37.787,34.586 38.494,34.586 ccw(c38.494,34.723) 38.631,34.723 38.631,34.753 ccw(c38.494,34.753) 38.494,34.89 37.65,34.89 37.257,34.89 cw(c37.257,35.027) 37.12,35.027 37.12,35.057 cw(c37.257,35.057) 37.257,35.194 37.65,35.194 38.494,35.194 ccw(c38.494,35.331) 38.631,35.331 38.631,35.361 ccw(c38.494,35.361) 38.494,35.498 37.787,35.498 cw(c37.787,35.635) 37.65,35.635 37.65,35.65 37.65,35.85 37.9,36.1 38.9,36.1 39.098,35.902 39.098,34.333 39.481,33.95 40.2,33.95 40.5,33.65 40.5,33.15 40.875,32.775 40.875,31.875 ; 40.875,31.55 40.875,31.875 ; v1(48.375,22.5) 47.631,22.5 46.298,23.833 46.298,24.176 40.875,29.599 40.875,31.875
  Bottom Layer w0.2: v1(48.375,22.5) R60.1@49.02,22.5 49.02,22.355 49.5,21.875 v1(52.625,21.875)
RGMII_RD1: R61.1 U1.AB3 U10.31 | length 43
  Top Layer w0.2: U10.31@35.325,33 35.875,33 36.125,33.25 36.636,33.25 37.261,32.625 39.375,32.625 v1(39.625,32.375) ; v1(48.375,20.5) U1.AB3@51.5,20.5
  Layer 8 w0.103: v1(39.625,32.375) 39.229,32.771 37.854,32.771 37.15,33.475 35.2,33.475 34.75,33.025 34.75,32.535 ccw(c34.887,32.535) 34.887,32.398 34.982,32.398 cw(c34.982,32.261) 35.119,32.261 35.119,32.231 cw(c34.982,32.231) 34.982,32.094 34.518,32.094 ccw(c34.518,31.957) 34.381,31.957 34.381,31.927 ccw(c34.518,31.927) 34.518,31.79 34.982,31.79 cw(c34.982,31.653) 35.119,31.653 35.119,31.623 cw(c34.982,31.623) 34.982,31.486 34.518,31.486 ccw(c34.518,31.349) 34.381,31.349 34.381,31.319 ccw(c34.518,31.319) 34.518,31.182 34.982,31.182 cw(c34.982,31.045) 35.119,31.045 35.119,31.015 cw(c34.982,31.015) 34.982,30.878 34.518,30.878 ccw(c34.518,30.741) 34.381,30.741 34.381,30.711 ccw(c34.518,30.711) 34.518,30.574 34.613,30.574 cw(c34.613,30.437) 34.75,30.437 34.75,29.05 35,28.8 35.675,28.8 35.875,29 35.875,30.8 36.15,31.075 37.75,31.075 37.9,30.925 37.9,29.35 38.95,28.3 40.269,28.3 47.148,21.421 47.148,20.833 47.481,20.5 v1(48.375,20.5)
  Bottom Layer w0.2: v1(48.375,20.5) R61.1@49.02,20.5
RGMII_RD2: R62.1 U1.AC4 U10.28 | length 43
  Top Layer w0.2: U10.28@35.325,31.5 36,31.5 36.375,31.125 39.625,31.125 v1(40.25,31.75) ; v1(52.605,18.625) 53.375,18.625 U1.AC4@53.5,18.5
  Layer 10 w0.103: v1(40.25,31.75) 40.898,31.102 40.898,30.133 41,30.031 41,29.302 42.69,27.613 42.69,26.91 42.7,26.9 42.7,26 43.2,25.5 43.211,25.489 ccw(c43.307,25.586) 43.404,25.489 43.492,25.577 cw(c43.589,25.48) 43.685,25.577 43.707,25.556 cw(c43.61,25.459) 43.707,25.362 43.522,25.178 43.338,24.993 ccw(c43.435,24.896) 43.338,24.8 43.359,24.778 ccw(c43.456,24.875) 43.553,24.778 43.737,24.963 43.922,25.147 cw(c44.019,25.05) 44.115,25.147 44.137,25.126 cw(c44.04,25.029) 44.137,24.932 43.952,24.748 43.768,24.563 ccw(c43.865,24.466) 43.768,24.37 43.789,24.348 ccw(c43.886,24.445) 43.983,24.348 44.167,24.533 44.352,24.717 cw(c44.449,24.62) 44.545,24.717 44.567,24.696 cw(c44.47,24.599) 44.567,24.502 44.479,24.414 ccw(c44.576,24.318) 44.479,24.221 45.05,23.65 45.25,23.45 45.975,23.45 47.1,22.325 47.1,19.7 46.925,19.525 46.275,19.525 46.15,19.65 46.15,22.625 45.875,22.9 45.35,22.9 45.225,22.775 45.225,20.725 44.925,20.425 44.925,18.825 45.125,18.625 v1(52.605,18.625)
  Bottom Layer w0.2: v1(52.605,18.625) 53.21,18.02 R62.1@53.5,18.02
RGMII_RD3: R63.1 U1.AC5 U10.27 | length 41.6
  Top Layer w0.2: U10.27@35.325,31 36,31 36.25,30.75 39.625,30.75 v1(40.125,30.25) ; v1(54.95,19.75) 55.5,19.2 U1.AC5@55.5,18.5
  Layer 8 w0.103: v1(40.125,30.25) 40.125,30.95 40,31.075 39.3,31.075 39.15,30.925 39.15,30.475 40.925,28.7 41.369,28.7 43.684,26.384 44.26,25.809 cw(c44.163,25.712) 44.26,25.615 43.988,25.344 ccw(c44.085,25.247) 43.988,25.151 44.01,25.129 ccw(c44.107,25.226) 44.203,25.129 44.475,25.401 cw(c44.571,25.304) 44.668,25.401 44.69,25.379 cw(c44.593,25.282) 44.69,25.186 44.418,24.914 ccw(c44.515,24.818) 44.418,24.721 44.44,24.699 ccw(c44.536,24.796) 44.633,24.699 44.904,24.971 cw(c45.001,24.874) 45.098,24.971 45.119,24.949 cw(c45.023,24.852) 45.119,24.756 44.848,24.484 ccw(c44.945,24.388) 44.848,24.291 44.87,24.269 ccw(c44.966,24.366) 45.063,24.269 45.334,24.541 cw(c45.431,24.444) 45.528,24.541 45.549,24.519 cw(c45.453,24.422) 45.549,24.326 45.278,24.054 ccw(c45.375,23.958) 45.278,23.861 45.3,23.84 ccw(c45.396,23.936) 45.493,23.839 45.764,24.111 cw(c45.861,24.014) 45.958,24.111 45.969,24.1 46.069,24 46.069,23.739 49.085,20.723 49.667,20.723 49.902,20.958 49.902,21.798 49.9,21.8 49.9,24.575 50.125,24.8 50.725,24.8 51,24.525 51,22.875 51.175,22.7 51.975,22.7 52.1,22.575 52.1,21.5 52.625,20.975 v1(52.625,20.5)
  Bottom Layer w0.2: R63.1@51.98,20.5 v1(52.625,20.5) 53.375,19.75 v1(54.95,19.75)
RGMII_REF_CLK: C104.1 R26.1 R27.2 U1.Y1 | length 4.4
  Top Layer w0.2: v1(46.775,24.6) 46.875,24.5 U1.Y1@47.5,24.5
  Bottom Layer w0.2: C104.1@46.75,25.49 46.75,24.625 v1(46.775,24.6) ; R26.1@47.92,24.3 47.075,24.3 v1(46.775,24.6) ; R27.2@47.92,25.35 47.525,25.35 v1(46.775,24.6)
RGMII_RESET_N: U1.P2 U10.42 | length 22.9
  Top Layer w0.125: U10.42@32.125,36.2 32.125,36.738 33.787,38.401 33.787,39.287 34.1,39.6 v1(35.65,39.6) ; v1(48.7,36) 49.2,36.5 U1.P2@49.5,36.5
  Bottom Layer w0.125: v1(35.65,39.6) 37.65,39.6 38.2,39.05 39.4,39.05 40.3,39.95 41.649,39.95 43.649,37.95 48.213,37.95 48.55,37.613 48.55,36.15 v1(48.7,36)
RGMII_RX_CTL: R58.1 R59.1 U1.V4 U10.33 | length 45.4
  Top Layer w0.2: U10.33@35.325,34 36,34 37.125,34 37.625,33.5 40.092,33.5 41.3,32.292 v1(41.3,32.05) ; v1(50.625,26.5) 50.625,27 51.125,27.5 52.5,27.5 U1.V4@53.5,28.5 v1(51.98,29.23)
  Layer 8 w0.103: v1(41.3,32.05) 41.375,31.975 41.375,31.175 41.55,31 41.775,31 42.75,31 43.525,30.225 43.75,30.225 43.765,30.225 ccw(c43.765,30.362) 43.902,30.362 43.902,31.83 cw(c44.039,31.83) 44.039,31.966 44.069,31.966 cw(c44.069,31.83) 44.206,31.83 44.206,30.225 44.206,28.62 ccw(c44.343,28.62) 44.343,28.484 44.373,28.484 ccw(c44.373,28.62) 44.51,28.62 44.51,30.225 44.51,31.83 cw(c44.647,31.83) 44.647,31.966 44.677,31.966 cw(c44.677,31.83) 44.814,31.83 44.814,30.225 44.814,28.62 ccw(c44.951,28.62) 44.951,28.484 44.981,28.484 ccw(c44.981,28.62) 45.118,28.62 45.118,30.225 45.118,30.498 cw(c45.255,30.498) 45.255,30.634 45.285,30.634 cw(c45.285,30.498) 45.422,30.498 45.422,30.225 45.422,28.62 ccw(c45.559,28.62) 45.559,28.484 45.589,28.484 ccw(c45.589,28.62) 45.726,28.62 45.726,30.101 cw(c45.85,30.101) 45.85,30.225 46.15,30.225 46.35,30.025 46.35,27.4 47.675,26.075 50.2,26.075 v1(50.625,26.5)
  Bottom Layer w0.2: R59.1@49.98,26.5 v1(50.625,26.5) ; R58.1@51.98,28.5 v1(51.98,29.23)
RGMII_RXC: R57.1 U1.AD5 U10.35 | length 43.4
  Top Layer w0.2: U10.35@35.325,35 36,35 36.125,35.125 39.38,35.125 39.511,35.125 40.086,34.55 v1(40.25,34.55) ; U1.AD5@55.5,16.5 56.6,15.4 v1(57.2,15.4)
  Layer 10 w0.103: v1(40.25,34.55) 40.175,34.55 39.525,33.9 38.775,33.9 38.325,33.45 38.325,31.3 42.21,27.415 42.21,24.315 43.7,22.825 43.7,21.225 44.325,20.6 44.325,18.6 44.85,18.075 48.525,18.075 48.775,17.825 48.775,16.925 48.9,16.8 49.117,16.8 50.167,15.75 55.35,15.75 55.7,15.4 v1(57.2,15.4)
  Bottom Layer w0.2: v1(57.2,15.4) 57.2,15.992 57.908,16.7 R57.1@57.92,16.7
RGMII_TD0: U1.U5 U10.19 | length 40.1
  Top Layer w0.2: U10.19@32.125,29.3 32.125,26.125 v1(32.375,25.875) ; U1.U5@55.5,30.5 v1(56,29.875)
  Layer 8 w0.103: v1(32.375,25.875) 32.375,26.75 32.925,27.3 34.525,27.3 34.946,26.879 37.354,26.879 37.575,27.1 38.5,27.1 39.646,25.954 41.704,25.954 47.56,20.098 52.792,20.098 53.161,20.467 53.161,23.211 53.95,24 53.95,27.828 55.781,29.659 55.784,29.659 v1(56,29.875)
RGMII_TD1: U1.V5 U10.20 | length 40.1
  Top Layer w0.2: U10.20@32.625,29.3 32.625,28.75 32.5,28.625 32.5,26.525 33.025,26 v1(33.375,26) ; U1.V5@55.5,28.5 v1(56.125,27.875)
  Layer 8 w0.103: v1(33.375,26) 33.625,26.25 37.125,26.25 37.45,25.925 38.55,25.925 38.95,25.525 38.95,24.875 40.025,23.8 43.21,23.8 47.66,19.35 48.45,19.35 48.6,19.2 48.6,18.494 48.869,18.225 50.275,18.225 51.4,19.35 52.691,19.35 53.619,20.278 53.619,22.244 56.825,25.45 56.825,25.65 56.825,25.665 ccw(c56.688,25.665) 56.688,25.802 56.45,25.802 cw(c56.45,25.939) 56.314,25.939 56.314,25.969 cw(c56.45,25.969) 56.45,26.106 56.688,26.106 ccw(c56.688,26.243) 56.825,26.243 56.825,27.175 v1(56.125,27.875)
RGMII_TD2: U1.Y5 U10.21 | length 40
  Top Layer w0.2: v1(33.125,26.875) 32.875,27.125 32.875,28.5 33.125,28.75 U10.21@33.125,29.3 ; U1.Y5@55.5,24.5 v1(56,25.25)
  Layer 8 w0.103: v1(33.125,26.875) 33.45,26.55 37.475,26.55 37.725,26.8 38.35,26.8 39.7,25.45 39.711,25.439 ccw(c39.807,25.536) 39.904,25.439 40.15,25.685 cw(c40.247,25.588) 40.343,25.685 40.365,25.663 cw(c40.268,25.567) 40.365,25.47 40.119,25.224 ccw(c40.216,25.128) 40.119,25.031 40.425,24.725 42.609,24.725 47.709,19.625 48.875,19.625 49.1,19.4 49.1,19.231 49.583,18.748 50.474,18.748 51.351,19.625 52.642,19.625 53.39,20.373 53.39,22.64 54.35,23.6 54.35,27.175 54.65,27.475 54.975,27.475 55.275,27.175 55.275,25.475 55.5,25.25 v1(56,25.25)
RGMII_TD3: U1.AA5 U10.22 | length 40.1
  Top Layer w0.2: U10.22@33.625,29.3 33.625,28.708 34,28.333 34,25.625 34.375,25.25 37.375,25.25 39.5,23.125 v1(40.375,23.125) ; U1.AA5@55.5,22.5 v1(56,23.125)
  Layer 8 w0.103: v1(40.375,23.125) 40.7,23.125 40.715,23.125 ccw(c40.715,23.262) 40.852,23.262 40.852,23.408 cw(c40.989,23.408) 40.989,23.545 41.019,23.545 cw(c41.019,23.408) 41.156,23.408 41.156,23.125 41.156,22.977 ccw(c41.293,22.977) 41.293,22.84 41.323,22.84 ccw(c41.323,22.977) 41.46,22.977 41.46,23.125 41.46,23.408 cw(c41.597,23.408) 41.597,23.545 41.627,23.545 cw(c41.627,23.408) 41.764,23.408 41.764,23.262 ccw(c41.901,23.262) 41.901,23.125 43.55,23.125 43.561,23.125 48.761,17.925 50.375,17.925 51.525,19.075 52.74,19.075 53.848,20.183 53.848,21.617 54.233,22.002 54.567,22.002 55.35,21.219 55.35,20.425 55.45,20.325 55.85,20.325 56,20.475 56,21.525 56.175,21.7 57,21.7 57.325,22.025 57.325,22.725 56.925,23.125 v1(56,23.125)
RGMII_TX_CTL: U1.W4 U10.25 | length 41.5
  Top Layer w0.2: U10.25@35.375,29.95 35.375,29.6 35.85,29.125 36.5,29.125 36.875,28.75 38.125,28.75 38.75,28.125 v1(38.75,27.5) ; v1(53,25.75) U1.W4@53.5,26.5
  Layer 3 w0.103: v1(38.75,27.5) 38.75,25.05 39.15,24.65 41.175,24.65 41.55,25.025 41.55,26.5 41.75,26.7 44.925,26.7 44.998,26.773 44.998,27.817 45.233,28.052 46.583,28.052 cw(c46.583,27.915) 46.72,27.915 46.72,26.264 ccw(c46.857,26.264) 46.857,26.127 46.887,26.127 ccw(c46.887,26.264) 47.024,26.264 47.024,27.915 cw(c47.161,27.915) 47.161,28.052 47.191,28.052 cw(c47.191,27.915) 47.328,27.915 47.328,26.264 ccw(c47.465,26.264) 47.465,26.127 47.495,26.127 ccw(c47.495,26.264) 47.632,26.264 47.632,28.276 cw(c47.769,28.276) 47.769,28.413 47.799,28.413 cw(c47.799,28.276) 47.936,28.276 47.936,26.94 ccw(c48.073,26.94) 48.073,26.803 48.103,26.803 ccw(c48.103,26.94) 48.24,26.94 48.24,27.915 cw(c48.377,27.915) 48.377,28.052 48.407,28.052 cw(c48.407,27.915) 48.544,27.915 48.544,27.083 ccw(c48.681,27.083) 48.681,26.946 48.711,26.946 ccw(c48.711,27.083) 48.848,27.083 48.848,27.915 cw(c48.985,27.915) 48.985,28.052 49.198,28.052 49.725,27.525 49.725,25.25 50.35,24.625 52.65,24.625 53,24.975 v1(53,25.75)
RGMII_TXC: U1.U4 U10.24 | length 41.6
  Top Layer w0.2: U10.24@34.625,29.3 34.625,29 34.875,28.75 36.375,28.75 37.25,27.875 v1(38,27.875) ; v1(52.625,30.375) U1.U4@53.5,30.5
  Layer 3 w0.103: v1(38,27.875) 38.25,28.125 39.125,28.125 39.3,27.95 39.3,26.8 39.475,26.625 39.8,26.625 39.95,26.775 39.95,28.125 40.225,28.4 40.565,28.4 ccw(c40.565,28.536) 40.701,28.536 40.701,29.039 cw(c40.838,29.039) 40.838,29.176 40.868,29.176 cw(c40.868,29.039) 41.004,29.039 41.004,27.761 ccw(c41.141,27.761) 41.141,27.624 41.171,27.624 ccw(c41.171,27.761) 41.307,27.761 41.307,29.039 cw(c41.444,29.039) 41.444,29.176 41.474,29.176 cw(c41.474,29.039) 41.61,29.039 41.61,27.761 ccw(c41.747,27.761) 41.747,27.624 41.777,27.624 ccw(c41.777,27.761) 41.913,27.761 41.913,29.039 cw(c42.05,29.039) 42.05,29.176 42.08,29.176 cw(c42.08,29.039) 42.216,29.039 42.216,27.761 ccw(c42.353,27.761) 42.353,27.624 42.383,27.624 ccw(c42.383,27.761) 42.519,27.761 42.519,28.767 cw(c42.656,28.767) 42.656,28.903 42.686,28.903 cw(c42.686,28.767) 42.822,28.767 42.822,28.536 ccw(c42.959,28.536) 42.959,28.4 47.3,28.4 47.56,28.66 48.34,28.66 48.675,28.325 49.375,28.325 49.5,28.45 49.5,32.525 49.975,33 51.85,33 51.95,32.9 51.95,32.5 51.825,32.375 50.881,32.375 50.473,31.967 50.473,31.008 50.783,30.698 51.423,30.698 51.675,30.95 52.05,30.95 v1(52.625,30.375)
RS232_1_CTS_N: J29.4 U8.6 | length 33.4
  Top Layer w0.125: v1(28.275,55.605) 28.325,55.555 U8.6@28.325,54.005
  Layer 10 w0.125: J29.4@2.2,52.25 2.45,52.25 3.337,53.137 3.337,55.534 5.416,57.612 7.309,57.612 8.809,59.112 18.354,59.112 19.317,58.15 21.331,58.15 21.565,57.916 22.82,57.916 24.586,56.15 27.73,56.15 v1(28.275,55.605)
RS232_1_RTS_N: J29.3 U8.11 | length 38.6
  Top Layer w0.125: 31.175,55.455 31.575,55.055 U8.11@31.575,54.005
  Layer 10 w0.125: J29.3@2.2,51 2.2,51.229 3.587,52.616 3.587,55.43 5.52,57.362 7.412,57.362 8.912,58.862 18.251,58.862 19.213,57.9 21.15,57.9 22.45,56.6 22.45,55.754 23.304,54.9 24.7,54.9 25.65,55.85 27.2,55.85 27.858,55.192 29.192,55.192 29.75,55.75 30.65,55.75 v1(30.95,55.45)
RS232_1_RX: J29.2 U8.5 | length 35.2
  Top Layer w0.125: v1(27.05,55.4) 27.343,55.4 27.675,55.068 U8.5@27.675,54.005
  Layer 10 w0.125: J29.2@2.2,49.75 3.064,50.614 3.064,51.739 3.837,52.513 3.837,55.327 5.623,57.112 7.562,57.112 9.062,58.612 18.147,58.612 19.11,57.65 21.046,57.65 22.2,56.496 22.2,55.65 23.2,54.65 26.478,54.65 27.05,55.222 v1(27.05,55.4)
RS232_1_TX: J29.1 U8.10 | length 41.7
  Top Layer w0.125: v1(29.925,55.155) 30.662,55.155 30.925,54.892 U8.10@30.925,54.005
  Layer 10 w0.125: J29.1@2.2,48.5 3.314,49.614 3.314,51.636 4.087,52.409 4.087,55.223 4.539,55.675 11.143,55.675 13.818,58.35 15.467,58.35 15.479,58.363 15.821,58.363 15.833,58.35 18.056,58.35 19.006,57.4 20.943,57.4 21.95,56.393 21.95,53.507 22.757,52.7 24.2,52.7 25,53.5 28.27,53.5 v1(29.925,55.155)
RS232_3_CTS_N: J29.9 U9.5 | length 39.1
  Top Layer w0.125: U9.5@37.875,55.85 v1(37.875,56.975)
  Layer 10 w0.125: J29.9@2.2,58.5 2.312,58.612 6.895,58.612 8.395,60.112 18.769,60.112 19.731,59.15 21.745,59.15 21.979,58.916 23.234,58.916 24.95,57.2 32.05,57.2 32.688,56.562 37.462,56.562 v1(37.875,56.975)
RS232_3_RTS_N: J29.8 U9.10 | length 42.9
  Top Layer w0.125: U9.10@41.125,55.85 v1(41.125,56.975)
  Layer 10 w0.125: J29.8@2.2,57.25 3.8,57.25 4.912,58.362 6.998,58.362 8.498,59.862 18.665,59.862 19.627,58.9 21.641,58.9 21.875,58.666 23.13,58.666 24.846,56.95 31.946,56.95 32.584,56.312 40.462,56.312 v1(41.125,56.975)
RS232_3_RX: J29.7 U9.4 | length 40.1
  Top Layer w0.125: U9.4@37.225,55.85 37.25,55.825 v1(37.25,54.7)
  Layer 10 w0.125: J29.7@2.2,56 3.05,56 5.162,58.112 7.102,58.112 8.602,59.612 18.561,59.612 19.524,58.65 21.538,58.65 21.772,58.416 23.027,58.416 24.743,56.7 31.843,56.7 34.23,54.312 36.862,54.312 v1(37.25,54.7)
RS232_3_TX: J29.6 U9.9 | length 43.8
  Top Layer w0.125: v1(40.475,54.725) U9.9@40.475,55.85
  Layer 10 w0.125: J29.6@2.2,54.75 5.312,57.862 7.205,57.862 8.705,59.362 18.458,59.362 19.42,58.4 21.434,58.4 21.668,58.166 22.923,58.166 24.639,56.45 31.739,56.45 34.127,54.062 39.812,54.062 v1(40.475,54.725)
RST: R77.2 R125.1 R126.1 | length 95.2
  Layer 8 w0.125: v1(25,16.05) 25.9,16.05 26.8,16.95 29.2,16.95 31.2,14.95 37.65,14.95 38.6,15.9 41.239,15.9 48.2,8.939 48.2,6.8 48.663,6.337 49.046,6.337 49.288,6.579 49.288,6.746 51.242,8.7 59.2,8.7 62.675,12.175 64.625,12.175 69.25,7.55 74.4,7.55 76.6,9.75 78.8,9.75 83.4,14.35 90,14.35 91.7,16.05 v1(92,16.05)
  Layer 3 w0.125: v1(19.15,21.5) 19.15,21.1 19.437,20.813 23.737,20.813 25,19.55 v1(25,16.05)
  Bottom Layer w0.125: R77.2@18.38,21.5 v1(19.15,21.5) ; v1(92,16.05) 92,16.35 92.28,16.63 R126.1@92.28,17.2 R125.1@93.32,17.2
SATA_RX_N: C16.1 U1.G19 | length 14.8
  Top Layer w0.104: U1.G19@83.5,50.5 v1(84.125,49.875)
  Layer 3 w0.093: v1(84.125,49.875) 84.35,49.65 84.775,49.65 85.538,50.413 85.538,61.537 v1(85.375,61.7)
  Bottom Layer w0.104: C16.1@85.125,62.415 85.375,62.165 v1@85.375,61.75
SATA_RX_P: C17.1 U1.H19 | length 15.3
  Top Layer w0.104: U1.H19@83.5,48.5 v1(84.125,49.125)
  Layer 3 w0.093: v1(84.125,49.125) 84.35,49.35 84.899,49.35 85.838,50.288 85.838,61.538 v1(86,61.7)
  Bottom Layer w0.104: v1@86,61.75 86,62.165 C17.1@86.25,62.415
SATA_TX_N: C15.1 U1.D19 | length 9.3
  Top Layer w0.104: v1(82.875,55.875) 83.425,55.875 83.5,55.95 U1.D19@83.5,56.5
  Layer 3 w0.093: v1(82.75,61.75) 82.588,61.588 82.588,61.026 81.625,60.063 81.625,56.575 82.55,55.65 82.65,55.65 v1(82.875,55.875)
  Bottom Layer w0.104: v1(82.75,61.75) 82.75,62.165 C15.1@83,62.415
SATA_TX_P: C14.1 U1.E19 | length 9.5
  Top Layer w0.104: v1(82.875,55.125) U1.E19@83.5,54.5
  Layer 3 w0.093: v1(82.125,61.75) 82.288,61.587 82.288,61.15 81.325,60.188 81.325,56.451 82.426,55.35 82.65,55.35 v1(82.875,55.125)
  Bottom Layer w0.104: C14.1@81.875,62.415 82.125,62.165 v1(82.125,61.75)
SATARX_N: C16.2 J8.5 | length 6.4
  Bottom Layer w0.104: C16.2@85.125,63.335 85.56,63.77 85.56,64.756 87.137,66.333 87.137,68.217 J8.5@86.63,68.725
SATARX_P: C17.2 J8.6 | length 6.4
  Bottom Layer w0.104: C17.2@86.25,63.335 85.815,63.77 85.815,64.65 87.392,66.227 87.392,68.217 J8.6@87.9,68.725
SATATX_N: C15.2 J8.3 | length 6.2
  Bottom Layer w0.104: C15.2@83,63.335 82.565,63.77 82.565,64.7 83.582,65.718 83.582,68.217 J8.3@84.09,68.725
SATATX_P: C14.2 J8.2 | length 6.2
  Bottom Layer w0.104: C14.2@81.875,63.335 82.31,63.77 82.31,64.806 83.327,65.823 83.327,68.217 J8.2@82.82,68.725
SD2_CLK: R35.1 U1.K22 | length 3.9
  Top Layer w0.2: U1.K22@89.5,44.5 v1(89.5,45.25)
  Bottom Layer w0.2: R35.1@87.77,47.65 87.77,46.98 v1(89.5,45.25)
SD2_CMD: J7.3 R30.1 U1.M20 | length 68.1
  Top Layer w0.2: v1(84.875,41.125) U1.M20@85.5,40.5
  Layer 3 w0.103: v1(74.75,6.375) 75.4,7.025 75.4,9.525 84.038,18.163 84.038,18.965 ccw(c83.901,18.965) 83.901,19.102 83.584,19.102 cw(c83.584,19.239) 83.448,19.239 83.448,19.269 cw(c83.584,19.269) 83.584,19.406 84.491,19.406 ccw(c84.491,19.543) 84.627,19.543 84.627,19.573 ccw(c84.491,19.573) 84.491,19.71 83.584,19.71 cw(c83.584,19.847) 83.448,19.847 83.448,19.877 cw(c83.584,19.877) 83.584,20.014 84.491,20.014 ccw(c84.491,20.151) 84.627,20.151 84.627,20.181 ccw(c84.491,20.181) 84.491,20.318 83.584,20.318 cw(c83.584,20.455) 83.448,20.455 83.448,20.485 cw(c83.584,20.485) 83.584,20.622 84.491,20.622 ccw(c84.491,20.759) 84.627,20.759 84.627,20.789 ccw(c84.491,20.789) 84.491,20.926 83.584,20.926 cw(c83.584,21.063) 83.448,21.063 83.448,21.093 cw(c83.584,21.093) 83.584,21.23 84.491,21.23 ccw(c84.491,21.367) 84.627,21.367 84.627,21.397 ccw(c84.491,21.397) 84.491,21.534 83.584,21.534 cw(c83.584,21.671) 83.448,21.671 83.448,21.701 cw(c83.584,21.701) 83.584,21.838 84.491,21.838 ccw(c84.491,21.975) 84.627,21.975 84.627,22.005 ccw(c84.491,22.005) 84.491,22.142 83.584,22.142 cw(c83.584,22.279) 83.448,22.279 83.448,22.309 cw(c83.584,22.309) 83.584,22.446 84.491,22.446 ccw(c84.491,22.583) 84.627,22.583 84.627,22.613 ccw(c84.491,22.613) 84.491,22.75 83.584,22.75 cw(c83.584,22.887) 83.448,22.887 83.448,22.917 cw(c83.584,22.917) 83.584,23.054 84.491,23.054 ccw(c84.491,23.191) 84.627,23.191 84.627,23.221 ccw(c84.491,23.221) 84.491,23.358 83.584,23.358 cw(c83.584,23.495) 83.448,23.495 83.448,23.525 cw(c83.584,23.525) 83.584,23.662 83.901,23.662 ccw(c83.901,23.799) 84.038,23.799 84.038,24.112 83,25.15 83,27.681 84.875,29.556 v1(84.875,41.125)
  Bottom Layer w0.2: R30.1@66.05,9.97 69.88,9.97 72.3,7.55 74.15,7.55 74.75,6.95 v1(74.75,6.375) J7.3@74.75,5.3
SD2_DAT0: J7.7 R34.1 U1.P24 | length 63.2
  Top Layer w0.2: U1.P24@93.5,36.5 93.575,36.5 v1(94.2,37.125)
  Layer 3 w0.103: v1(79.125,6.5) 81.625,6.5 85.25,10.125 87.425,10.125 90,12.7 90,13.515 ccw(c89.863,13.515) 89.863,13.652 89.546,13.652 cw(c89.546,13.789) 89.409,13.789 89.409,13.819 cw(c89.546,13.819) 89.546,13.956 90.454,13.956 ccw(c90.454,14.093) 90.591,14.093 90.591,14.123 ccw(c90.454,14.123) 90.454,14.26 89.546,14.26 cw(c89.546,14.397) 89.409,14.397 89.409,14.427 cw(c89.546,14.427) 89.546,14.564 90.454,14.564 ccw(c90.454,14.701) 90.591,14.701 90.591,14.731 ccw(c90.454,14.731) 90.454,14.868 89.546,14.868 cw(c89.546,15.005) 89.409,15.005 89.409,15.035 cw(c89.546,15.035) 89.546,15.172 90.454,15.172 ccw(c90.454,15.309) 90.591,15.309 90.591,15.339 ccw(c90.454,15.339) 90.454,15.476 89.546,15.476 cw(c89.546,15.613) 89.409,15.613 89.409,15.643 cw(c89.546,15.643) 89.546,15.78 90.454,15.78 ccw(c90.454,15.917) 90.591,15.917 90.591,15.947 ccw(c90.454,15.947) 90.454,16.084 89.546,16.084 cw(c89.546,16.221) 89.409,16.221 89.409,16.251 cw(c89.546,16.251) 89.546,16.388 90.454,16.388 ccw(c90.454,16.525) 90.591,16.525 90.591,16.555 ccw(c90.454,16.555) 90.454,16.692 89.546,16.692 cw(c89.546,16.829) 89.409,16.829 89.409,16.859 cw(c89.546,16.859) 89.546,16.996 90.454,16.996 ccw(c90.454,17.133) 90.591,17.133 90.591,17.163 ccw(c90.454,17.163) 90.454,17.3 89.546,17.3 cw(c89.546,17.437) 89.409,17.437 89.409,17.467 cw(c89.546,17.467) 89.546,17.604 90.454,17.604 ccw(c90.454,17.741) 90.591,17.741 90.591,17.771 ccw(c90.454,17.771) 90.454,17.908 89.571,17.908 cw(c89.571,18.045) 89.434,18.045 89.434,18.075 cw(c89.571,18.075) 89.571,18.212 89.863,18.212 ccw(c89.863,18.349) 90,18.349 90,20.35 93,23.35 93,31.625 93.625,32.25 93.625,36.625 v1@94.125,37.125
  Bottom Layer w0.2: J7.7@79.1,5.25 J7.7@79.125,5.275 ; v1(79.125,6.5) J7.7@79.125,5.275 ; R34.1@82.5,5.97 82.5,5.25 81.3,4.05 79.4,4.05 79.125,4.325 J7.7@79.125,5.275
